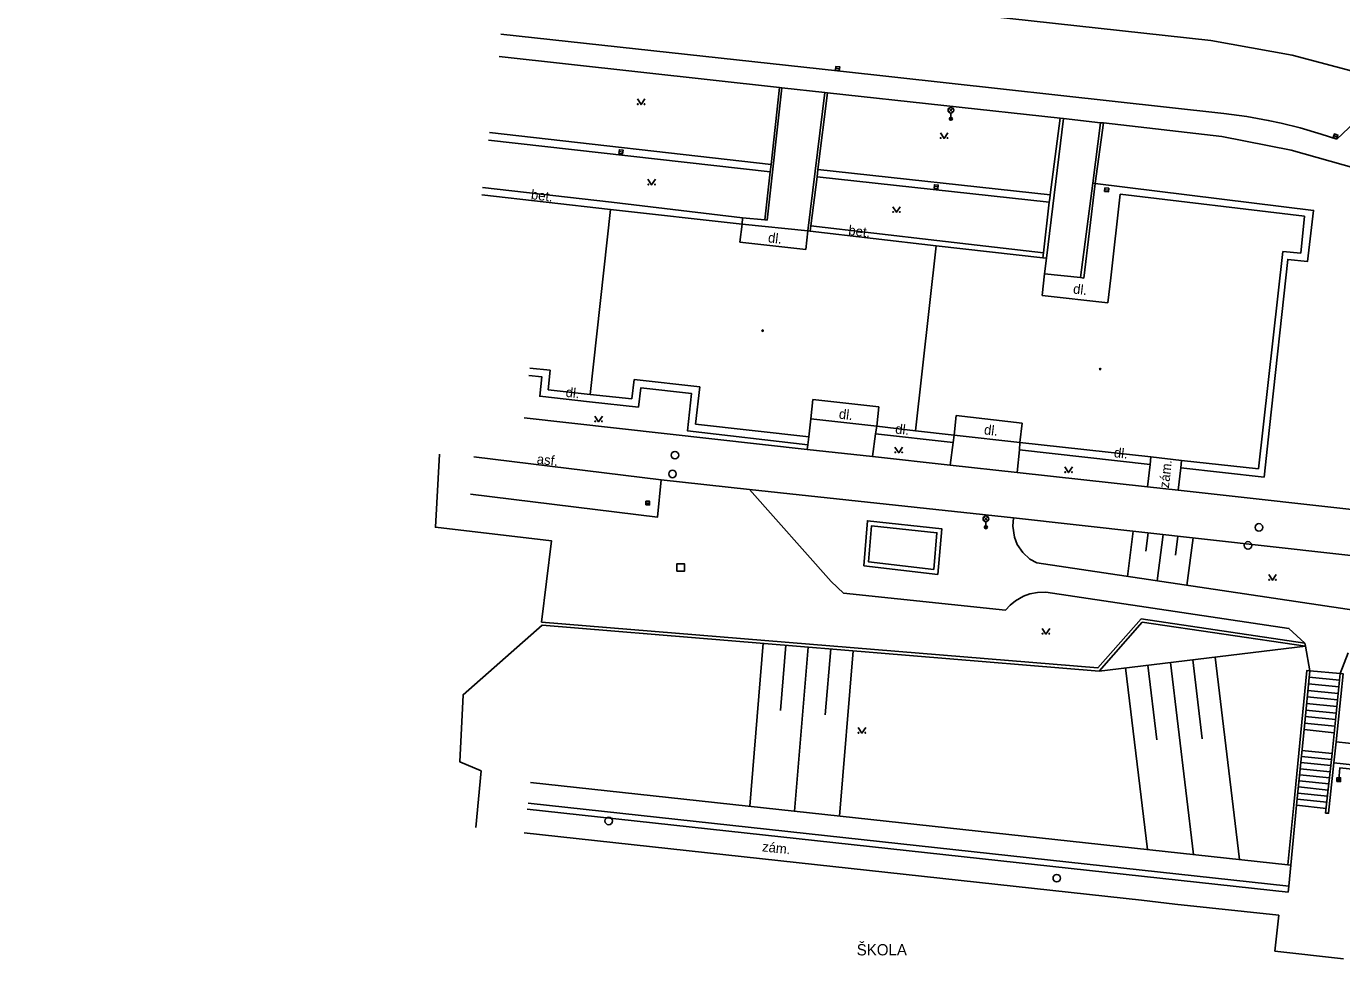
# Model space of a CAD drawing. Extents: x -602419 to -601554, y -1162937 to -1162362.
# Drawn here: x -602396.1 to -602308.5, y -1162561.2 to -1162499.1 of the extents above; entities that cross this region are included whole.
import ezdxf

# ---------------------------------------------------------------- set-up
doc = ezdxf.new("R2010")
doc.units = 0
doc.layers.add('Podklad', color=7, linetype='Continuous')

msp = doc.modelspace()

# ---------------------------------------------------------------- linework, layer by layer
at = {"layer": 'Podklad'}
for p, q in [((-602342.1642, -1162501.8759), (-602341.9158, -1162501.9041)), ((-602334.6325, -1162504.81), (-602334.3675, -1162504.545)), ((-602334.6325, -1162504.545), (-602334.3675, -1162504.81)), ((-602334.5, -1162504.865), (-602334.5, -1162505.24)), ((-602309.0086, -1162506.3704), (-602308.7714, -1162506.4494)), ((-602356.5842, -1162507.4261), (-602356.3358, -1162507.4539)), ((-602335.6044, -1162509.7581), (-602335.3556, -1162509.7819)), ((-602324.2544, -1162509.9681), (-602324.0056, -1162509.9919)), ((-602354.805, -1162530.83), (-602354.555, -1162530.83)), ((-602332.3025, -1162532.01), (-602332.0375, -1162531.745)), ((-602332.3025, -1162531.745), (-602332.0375, -1162532.01)), ((-602332.17, -1162532.065), (-602332.17, -1162532.44)), ((-602308.805, -1162549.25), (-602308.555, -1162549.25))]:
    msp.add_line(p, q, dxfattribs=at)
for points in [[(-602304.83, -1162502.84), (-602311.77, -1162501.0069), (-602317.2, -1162500.0369), (-602396.05, -1162491.38)], [(-602364.4699, -1162499.6), (-602342.04, -1162502.04)], [(-602364.58, -1162501.1), (-602345.9099, -1162503.15)], [(-602342.04, -1162502.04), (-602316.32, -1162504.89)], [(-602346.88, -1162511.98), (-602346.73, -1162511.99), (-602345.76, -1162503.17)], [(-602345.9099, -1162503.15), (-602346.4699, -1162508.28)], [(-602345.9099, -1162503.15), (-602345.76, -1162503.17)], [(-602342.89, -1162503.5), (-602345.76, -1162503.17)], [(-602308.8, -1162506.6), (-602304.83, -1162502.84)], [(-602355.37, -1162503.915), (-602355.12, -1162504.29), (-602354.87, -1162503.915)], [(-602342.89, -1162503.5), (-602344.02, -1162512.71)], [(-602342.7199, -1162503.52), (-602343.35, -1162508.61)], [(-602342.89, -1162503.5), (-602342.7199, -1162503.52)], [(-602342.7199, -1162503.52), (-602327.2199, -1162505.21)], [(-602316.32, -1162504.89), (-602314.79, -1162505.1), (-602313.37, -1162505.35), (-602312.51, -1162505.54), (-602311.24, -1162505.84), (-602309.86, -1162506.26), (-602308.8, -1162506.6)], [(-602328.14, -1162514.52), (-602327, -1162505.23)], [(-602327.2199, -1162505.21), (-602327.89, -1162510.3)], [(-602327.2199, -1162505.21), (-602327, -1162505.23)], [(-602327, -1162505.23), (-602324.54, -1162505.5)], [(-602325.06, -1162509.53), (-602324.54, -1162505.5)], [(-602324.35, -1162505.52), (-602324.9, -1162509.54)], [(-602324.54, -1162505.5), (-602324.35, -1162505.52)], [(-602324.35, -1162505.52), (-602316.4699, -1162506.42), (-602311.85, -1162507.32), (-602307.53, -1162508.55), (-602302.8, -1162510.24)], [(-602346.53, -1162508.78), (-602365.28, -1162506.6599)], [(-602365.2199, -1162506.1599), (-602346.4699, -1162508.28)], [(-602335.2, -1162506.175), (-602334.95, -1162506.55), (-602334.7, -1162506.175)], [(-602346.4699, -1162508.28), (-602346.53, -1162508.78)], [(-602354.67, -1162509.265), (-602354.42, -1162509.64), (-602354.17, -1162509.265)], [(-602346.53, -1162508.78), (-602346.88, -1162511.98)], [(-602343.4099, -1162509.11), (-602343.82, -1162512.37)], [(-602343.35, -1162508.61), (-602343.4099, -1162509.11)], [(-602327.95, -1162510.8), (-602343.4099, -1162509.11)], [(-602343.35, -1162508.61), (-602327.89, -1162510.3)], [(-602348.38, -1162511.84), (-602357.09, -1162510.79), (-602365.67, -1162509.81)], [(-602325.06, -1162509.53), (-602325.86, -1162515.81)], [(-602324.9, -1162509.55), (-602325.65, -1162515.85)], [(-602325.06, -1162509.53), (-602324.9, -1162509.55)], [(-602324.9, -1162509.54), (-602324.9, -1162509.55)], [(-602324.9, -1162509.55), (-602310.35, -1162511.34), (-602310.76, -1162514.75), (-602312.07, -1162514.61), (-602313.29, -1162525.8), (-602313.65, -1162529.1), (-602319.2, -1162528.49)], [(-602365.73, -1162510.31), (-602357.15, -1162511.29)], [(-602338.37, -1162511.0949), (-602338.12, -1162511.4699), (-602337.87, -1162511.0949)], [(-602327.95, -1162510.8), (-602328.33, -1162514.17)], [(-602327.92, -1162510.55), (-602327.95, -1162510.8)], [(-602327.89, -1162510.3), (-602327.92, -1162510.55)], [(-602323.85, -1162515.84), (-602323.23, -1162510.25)], [(-602323.23, -1162510.25), (-602310.96, -1162511.73)], [(-602357.15, -1162511.29), (-602358.52, -1162523.59)], [(-602357.15, -1162511.29), (-602348.4, -1162512.26)], [(-602348.38, -1162511.84), (-602348.4, -1162512.26)], [(-602346.88, -1162511.98), (-602348.38, -1162511.84)], [(-602310.96, -1162511.73), (-602311.21, -1162514.2)], [(-602348.4, -1162512.26), (-602348.54, -1162513.45)], [(-602344.02, -1162512.71), (-602348.4, -1162512.26)], [(-602344.1599, -1162513.94), (-602344.02, -1162512.71)], [(-602344.02, -1162512.71), (-602343.87, -1162512.73)], [(-602343.82, -1162512.37), (-602343.87, -1162512.73)], [(-602343.87, -1162512.73), (-602335.48, -1162513.7)], [(-602328.33, -1162514.17), (-602335.44, -1162513.34), (-602343.82, -1162512.37)], [(-602348.54, -1162513.45), (-602344.1599, -1162513.94)], [(-602335.48, -1162513.7), (-602336.86, -1162526.01)], [(-602335.48, -1162513.7), (-602328.37, -1162514.49)], [(-602328.33, -1162514.17), (-602328.37, -1162514.49)], [(-602328.37, -1162514.49), (-602328.14, -1162514.52)], [(-602328.14, -1162514.52), (-602328.26, -1162515.56)], [(-602312.4, -1162514.07), (-602314.02, -1162528.56)], [(-602311.21, -1162514.2), (-602312.4, -1162514.07)], [(-602328.26, -1162515.56), (-602328.42, -1162517.01)], [(-602328.26, -1162515.56), (-602325.86, -1162515.81)], [(-602325.65, -1162515.85), (-602325.86, -1162515.81)], [(-602324.04, -1162517.5), (-602323.85, -1162515.84)], [(-602328.42, -1162517.01), (-602324.04, -1162517.5)], [(-602344.02, -1162526.96), (-602352.04, -1162526.02), (-602351.76, -1162523.54), (-602355.15, -1162523.1599), (-602355.3, -1162524.44), (-602358.56, -1162524.09), (-602361.87, -1162523.7199), (-602361.7199, -1162522.43), (-602362.59, -1162522.33)], [(-602361.17, -1162521.99), (-602362.54, -1162521.84)], [(-602361.31, -1162523.28), (-602361.17, -1162521.99)], [(-602358.52, -1162523.59), (-602361.31, -1162523.28)], [(-602355.59, -1162522.61), (-602355.74, -1162523.9)], [(-602351.21, -1162523.1), (-602355.59, -1162522.61)], [(-602351.49, -1162525.58), (-602351.21, -1162523.1)], [(-602355.74, -1162523.9), (-602358.52, -1162523.59)], [(-602343.68, -1162523.94), (-602343.82, -1162525.23)], [(-602339.29, -1162524.43), (-602343.68, -1162523.94)], [(-602358.2, -1162525.0349), (-602357.95, -1162525.4099), (-602357.7, -1162525.0349)], [(-602339.44, -1162525.7199), (-602339.29, -1162524.43)], [(-602334.14, -1162525.01), (-602334.28, -1162526.3)], [(-602329.76, -1162525.5), (-602334.14, -1162525.01)], [(-602362.9099, -1162525.1599), (-602344.06, -1162527.26)], [(-602343.95, -1162526.43), (-602351.49, -1162525.58)], [(-602343.82, -1162525.23), (-602343.95, -1162526.43)], [(-602339.44, -1162525.7199), (-602343.82, -1162525.23)], [(-602339.51, -1162526.2199), (-602339.44, -1162525.7199)], [(-602336.86, -1162526.01), (-602339.44, -1162525.7199)], [(-602329.9, -1162526.79), (-602329.76, -1162525.5)], [(-602343.95, -1162526.43), (-602344.02, -1162526.96)], [(-602339.71, -1162527.74), (-602339.51, -1162526.2199)], [(-602334.35, -1162526.8), (-602339.51, -1162526.2199)], [(-602334.28, -1162526.3), (-602336.86, -1162526.01)], [(-602334.35, -1162526.8), (-602334.55, -1162528.31)], [(-602334.28, -1162526.3), (-602334.35, -1162526.8)], [(-602329.9, -1162526.79), (-602334.28, -1162526.3)], [(-602329.9, -1162526.79), (-602329.94, -1162527.29)], [(-602321.18, -1162527.76), (-602329.9, -1162526.79)], [(-602361.76, -1162538.76), (-602361.09, -1162533.34), (-602368.82, -1162532.44), (-602368.55, -1162527.58)], [(-602344.02, -1162526.96), (-602344.06, -1162527.26)], [(-602344.06, -1162527.26), (-602339.71, -1162527.74)], [(-602339.71, -1162527.74), (-602334.55, -1162528.31)], [(-602338.2199, -1162527.105), (-602337.9699, -1162527.48), (-602337.7199, -1162527.105)], [(-602329.94, -1162527.29), (-602330.08, -1162528.8)], [(-602321.24, -1162528.26), (-602329.94, -1162527.29)], [(-602353.78, -1162529.28), (-602366.25, -1162527.75)], [(-602334.55, -1162528.31), (-602330.08, -1162528.8)], [(-602326.9099, -1162528.425), (-602326.6599, -1162528.8), (-602326.4099, -1162528.425)], [(-602321.4, -1162529.76), (-602321.24, -1162528.26)], [(-602321.24, -1162528.26), (-602321.18, -1162527.76)], [(-602319.14, -1162527.99), (-602321.18, -1162527.76)], [(-602319.2, -1162528.49), (-602319.37, -1162529.98)], [(-602319.14, -1162527.99), (-602319.2, -1162528.49)], [(-602314.02, -1162528.56), (-602319.14, -1162527.99)], [(-602353.78, -1162529.28), (-602354.04, -1162531.77), (-602366.49, -1162530.23)], [(-602347.9, -1162529.92), (-602353.78, -1162529.28)], [(-602330.08, -1162528.8), (-602321.4, -1162529.76)], [(-602347.9, -1162529.92), (-602342.48, -1162536.05), (-602341.64, -1162536.82), (-602330.86, -1162537.9699)], [(-602330.32, -1162531.82), (-602347.9, -1162529.92)], [(-602321.4, -1162529.76), (-602319.37, -1162529.98)], [(-602319.37, -1162529.98), (-602305.62, -1162531.5)], [(-602340.3, -1162535.01), (-602340.06, -1162532.01), (-602335.11, -1162532.54), (-602335.37, -1162535.58), (-602340.3, -1162535.01)], [(-602330.32, -1162531.82), (-602330.37, -1162532.37), (-602330.27, -1162533.11), (-602330.08, -1162533.59), (-602329.7199, -1162534.13), (-602329.24, -1162534.57), (-602328.78, -1162534.82)], [(-602330.32, -1162531.82), (-602304.69, -1162534.67)], [(-602335.64, -1162535.25), (-602339.98, -1162534.75), (-602339.78, -1162532.34), (-602335.43, -1162532.81), (-602335.64, -1162535.25)], [(-602322.36, -1162532.7), (-602322.75, -1162535.7199)], [(-602321.37, -1162532.82), (-602321.52, -1162534.04)], [(-602320.37, -1162532.93), (-602320.77, -1162536.01)], [(-602319.38, -1162533.04), (-602319.54, -1162534.29)], [(-602318.38, -1162533.15), (-602318.79, -1162536.31)], [(-602305.15, -1162538.34), (-602328.78, -1162534.82)], [(-602313.34, -1162535.5949), (-602313.09, -1162535.9699), (-602312.84, -1162535.5949)], [(-602330.86, -1162537.9699), (-602330.55, -1162537.62), (-602330.19, -1162537.33), (-602329.67, -1162537.03), (-602329.24, -1162536.88), (-602328.73, -1162536.78), (-602328.18, -1162536.76)], [(-602328.18, -1162536.76), (-602312, -1162539.18), (-602310.93, -1162540.1599)], [(-602366.12, -1162552.43), (-602365.77, -1162548.67), (-602367.18, -1162548.07), (-602366.9699, -1162543.59), (-602361.7, -1162538.96), (-602324.63, -1162542.02)], [(-602361.76, -1162538.76), (-602324.71, -1162541.81), (-602321.84, -1162538.54), (-602310.93, -1162540.1599)], [(-602324.63, -1162542.02), (-602321.76, -1162538.76), (-602310.89, -1162540.36)], [(-602328.42, -1162539.175), (-602328.17, -1162539.55), (-602327.92, -1162539.175)], [(-602346.99, -1162540.17), (-602347.88, -1162551.02)], [(-602345.49, -1162540.3), (-602345.85, -1162544.65)], [(-602343.99, -1162540.42), (-602344.9, -1162551.34)], [(-602342.5, -1162540.54), (-602342.86, -1162544.93)], [(-602341.01, -1162540.67), (-602341.9099, -1162551.67)], [(-602324.63, -1162542.02), (-602310.89, -1162540.36)], [(-602310.93, -1162540.1599), (-602310.89, -1162540.36)], [(-602310.89, -1162540.36), (-602310.61, -1162542)], [(-602308.05, -1162540.81), (-602308.58, -1162542.19)], [(-602321.38, -1162541.63), (-602320.78, -1162546.6)], [(-602319.89, -1162541.45), (-602318.34, -1162554.24)], [(-602318.4, -1162541.27), (-602317.76, -1162546.52)], [(-602316.9099, -1162541.09), (-602315.28, -1162554.57)], [(-602322.87, -1162541.81), (-602321.4, -1162553.9)], [(-602311.67, -1162550.92), (-602310.81, -1162541.98), (-602310.61, -1162542)], [(-602310.61, -1162542), (-602310.99, -1162545.9099), (-602311.48, -1162550.94)], [(-602308.62, -1162542.62), (-602310.65, -1162542.43)], [(-602308.58, -1162542.19), (-602310.61, -1162542)], [(-602310.61, -1162542), (-602308.58, -1162542.19)], [(-602308.58, -1162542.19), (-602309.12, -1162547.5), (-602309.55, -1162551.4699), (-602309.35, -1162551.49), (-602309, -1162548.12)], [(-602308.85, -1162546.73), (-602308.38, -1162542.21), (-602308.58, -1162542.19)], [(-602308.71, -1162543.5), (-602310.74, -1162543.3)], [(-602310.7, -1162542.87), (-602308.67, -1162543.06)], [(-602308.8, -1162544.37), (-602310.82, -1162544.17)], [(-602310.78, -1162543.74), (-602308.76, -1162543.94)], [(-602308.89, -1162545.24), (-602310.9099, -1162545.04)], [(-602310.86, -1162544.61), (-602308.85, -1162544.81)], [(-602340.67, -1162545.775), (-602340.42, -1162546.15), (-602340.17, -1162545.775)], [(-602308.98, -1162546.12), (-602310.99, -1162545.9099)], [(-602310.95, -1162545.48), (-602308.93, -1162545.68)], [(-602309, -1162548.12), (-602308.85, -1162546.73)], [(-602308.85, -1162546.73), (-602281.76, -1162549.65), (-602281.62, -1162548.14), (-602278.98, -1162548.14)], [(-602309.1599, -1162547.9), (-602311.1599, -1162547.71)], [(-602311.13, -1162547.31), (-602309.12, -1162547.5)], [(-602309.25, -1162548.7199), (-602311.24, -1162548.52)], [(-602311.2, -1162548.11), (-602309.21, -1162548.31)], [(-602309, -1162548.12), (-602281.4, -1162551.1)], [(-602281.4, -1162551.1), (-602281.42, -1162551.4), (-602308.6, -1162548.46), (-602308.68, -1162549.25)], [(-602362.48, -1162549.43), (-602312.07, -1162554.92)], [(-602309.34, -1162549.53), (-602311.32, -1162549.33)], [(-602311.28, -1162548.92), (-602309.3, -1162549.12)], [(-602309.43, -1162550.34), (-602311.4, -1162550.14)], [(-602311.36, -1162549.73), (-602309.38, -1162549.94)], [(-602362.7, -1162551.2199), (-602312.05, -1162556.73), (-602312, -1162556.33)], [(-602312, -1162556.33), (-602362.65, -1162550.82)], [(-602311.67, -1162550.92), (-602312.07, -1162554.92)], [(-602311.48, -1162550.94), (-602311.87, -1162554.94)], [(-602309.52, -1162551.1599), (-602311.48, -1162550.94)], [(-602311.44, -1162550.54), (-602309.4699, -1162550.75)], [(-602362.9099, -1162552.78), (-602321.82, -1162557.27)], [(-602312.07, -1162554.92), (-602311.87, -1162554.94)], [(-602311.87, -1162554.94), (-602312, -1162556.33)], [(-602321.82, -1162557.27), (-602319.58, -1162557.53)], [(-602319.58, -1162557.53), (-602312.67, -1162558.28)], [(-602312.67, -1162558.28), (-602312.93, -1162560.67)], [(-602312.93, -1162560.67), (-602308.36, -1162561.17)]]:
    msp.add_lwpolyline(points, dxfattribs=at)
for points in [[(-602342.1783, -1162502.0001), (-602341.9299, -1162502.0283), (-602341.9017, -1162501.7799), (-602342.1501, -1162501.7517)], [(-602309.0481, -1162506.489), (-602308.8109, -1162506.568), (-602308.7319, -1162506.3308), (-602308.9691, -1162506.2518)], [(-602356.5981, -1162507.5503), (-602356.3497, -1162507.5781), (-602356.3219, -1162507.3297), (-602356.5703, -1162507.3019)], [(-602335.6163, -1162509.8826), (-602335.3674, -1162509.9063), (-602335.3437, -1162509.6574), (-602335.5926, -1162509.6337)], [(-602324.2663, -1162510.0925), (-602324.0175, -1162510.1163), (-602323.9937, -1162509.8675), (-602324.2425, -1162509.8437)], [(-602354.805, -1162530.955), (-602354.555, -1162530.955), (-602354.555, -1162530.705), (-602354.805, -1162530.705)], [(-602352.74, -1162535.37), (-602352.24, -1162535.37), (-602352.24, -1162534.87), (-602352.74, -1162534.87)], [(-602308.805, -1162549.375), (-602308.555, -1162549.375), (-602308.555, -1162549.125), (-602308.805, -1162549.125)]]:
    msp.add_lwpolyline(points, close=True, dxfattribs=at)
for centre, radius in [((-602355.3451, -1162504.2649), 0.025), ((-602354.8954, -1162504.2649), 0.025), ((-602334.5, -1162504.6775), 0.1875), ((-602334.5, -1162505.24), 0.1), ((-602334.5, -1162505.24), 0.0723), ((-602334.5, -1162505.24), 0.0438), ((-602335.1751, -1162506.5249), 0.025), ((-602334.7254, -1162506.5249), 0.025), ((-602354.6451, -1162509.6149), 0.025), ((-602354.1954, -1162509.6149), 0.025), ((-602338.3451, -1162511.4448), 0.025), ((-602337.8954, -1162511.4448), 0.025), ((-602347.03, -1162519.35), 0.045), ((-602347.03, -1162519.35), 0.0199), ((-602324.56, -1162521.9099), 0.045), ((-602324.56, -1162521.9099), 0.0199), ((-602358.1751, -1162525.3848), 0.025), ((-602357.7254, -1162525.3848), 0.025), ((-602352.87, -1162527.64), 0.25), ((-602338.195, -1162527.4549), 0.025), ((-602337.7453, -1162527.4549), 0.025), ((-602353.03, -1162528.89), 0.25), ((-602326.885, -1162528.7749), 0.025), ((-602326.4353, -1162528.7749), 0.025), ((-602332.17, -1162531.8775), 0.1875), ((-602332.17, -1162532.44), 0.1), ((-602332.17, -1162532.44), 0.0723), ((-602332.17, -1162532.44), 0.0438), ((-602313.99, -1162532.45), 0.25), ((-602314.7199, -1162533.65), 0.25), ((-602313.3151, -1162535.9448), 0.025), ((-602312.8654, -1162535.9448), 0.025), ((-602328.3951, -1162539.5249), 0.025), ((-602327.9454, -1162539.5249), 0.025), ((-602340.6451, -1162546.1249), 0.025), ((-602340.1954, -1162546.1249), 0.025), ((-602357.28, -1162552), 0.25), ((-602327.45, -1162555.81), 0.25)]:
    msp.add_circle(centre, radius, dxfattribs=at)

# ---------------------------------------------------------------- texts
for s, rotation, p in [('bet.', 353.12, (-602362.48, -1162510.59)), ('dl.', 353.12, (-602346.7, -1162513.46)), ('bet.', 353.12, (-602341.35, -1162512.9699)), ('dl.', 353.12, (-602326.39, -1162516.87)), ('dl.', 353.26, (-602360.17, -1162523.75)), ('dl.', 353.26, (-602341.98, -1162525.2)), ('dl.', 353.26, (-602338.23, -1162526.19)), ('dl.', 353.26, (-602332.32, -1162526.25)), ('asf.', 353.7, (-602362.09, -1162528.21)), ('dl.', 353.26, (-602323.67, -1162527.77)), (' zám.', 83.55, (-602320.02, -1162530.1)), (' zám.', 353.76, (-602347.33, -1162553.99))]:
    msp.add_text(s, height=0.65, rotation=rotation, dxfattribs=at).set_placement(p)
msp.add_text('ŠKOLA', height=0.75, dxfattribs=at).set_placement((-602340.77, -1162560.95))

doc.saveas('drawing.dxf')
